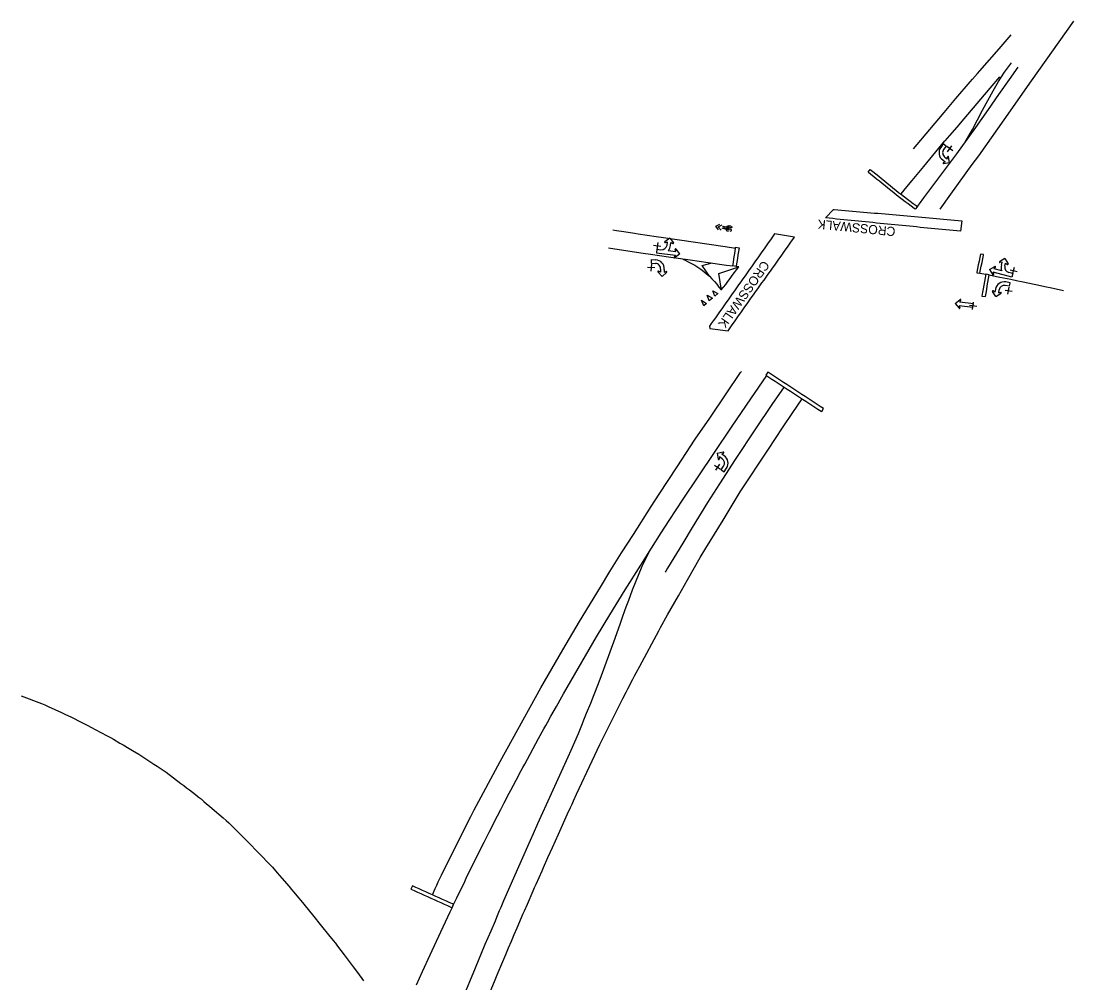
# Model space of a CAD drawing. Extents: x 1723992 to 1732080, y 650782 to 665122.
# Drawn here: x 1730247 to 1730822, y 652932 to 653458 of the extents above; entities that cross this region are included whole.
import ezdxf

# ---------------------------------------------------------------- set-up
doc = ezdxf.new("R2010")
doc.units = 0
doc.layers.add('SURVEY - TRAFFIC CONTROL - Pavement Marking - Points - Locators', color=7, linetype='Continuous')
doc.layers.add('SURVEY - TRAFFIC CONTROL - Pavement Marking with Text', color=7, linetype='Continuous')

msp = doc.modelspace()

# ---------------------------------------------------------------- linework, layer by layer
at = {"layer": 'SURVEY - TRAFFIC CONTROL - Pavement Marking - Points - Locators'}
for p, q in [((1730755.42, 653386.72), (1730752.19, 653389.08)), ((1730752.63, 653386.28), (1730754.98, 653389.52)), ((1730595.99, 653334.51), (1730592.02, 653335.01)), ((1730594.26, 653336.74), (1730593.75, 653332.77)), ((1730592.68, 653322.84), (1730588.68, 653323.09)), ((1730590.8, 653324.96), (1730590.56, 653320.97)), ((1730788.16, 653319.4), (1730789.16, 653323.27)), ((1730786.73, 653321.83), (1730790.6, 653320.83)), ((1730785.6, 653308.42), (1730786.31, 653312.36)), ((1730783.99, 653310.74), (1730787.92, 653310.04)), ((1730764.59, 653302.42), (1730768.56, 653301.89)), ((1730766.31, 653300.17), (1730766.84, 653304.14)), ((1730625.24, 653215.15), (1730628.55, 653212.89)), ((1730628.03, 653215.67), (1730625.76, 653212.37))]:
    msp.add_line(p, q, dxfattribs=at)
at = {"layer": 'SURVEY - TRAFFIC CONTROL - Pavement Marking with Text'}
for p, q in [((1730750.22, 653390.5), (1730748.87, 653388.65)), ((1730751.81, 653389.35), (1730750.22, 653390.5)), ((1730751.81, 653389.35), (1730750.46, 653387.49)), ((1730749.96, 653381.77), (1730751.27, 653380.82)), ((1730751.27, 653380.82), (1730750.22, 653380.18)), ((1730753.72, 653380.26), (1730750.38, 653379.73)), ((1730751.12, 653383.37), (1730752.42, 653382.42)), ((1730752.42, 653382.42), (1730752.71, 653383.61)), ((1730753.72, 653380.26), (1730753.19, 653383.59)), ((1730600.84, 653339.1), (1730598.17, 653337.03)), ((1730599.57, 653336.92), (1730598.38, 653336.6)), ((1730599.36, 653335.32), (1730599.57, 653336.92)), ((1730600.84, 653339.1), (1730602.91, 653336.43)), ((1730601.32, 653335.07), (1730601.52, 653336.68)), ((1730601.52, 653336.68), (1730602.59, 653336.07)), ((1730593.79, 653333.05), (1730593.54, 653331.1)), ((1730593.54, 653331.1), (1730603.97, 653329.77)), ((1730593.79, 653333.05), (1730596.06, 653332.76)), ((1730599.97, 653332.27), (1730604.22, 653331.73)), ((1730603.97, 653329.77), (1730603.36, 653328.71)), ((1730606.39, 653330.46), (1730603.72, 653328.39)), ((1730604.22, 653331.73), (1730603.9, 653332.91)), ((1730606.39, 653330.46), (1730604.33, 653333.13)), ((1730590.83, 653325.42), (1730590.95, 653327.38)), ((1730590.83, 653325.42), (1730593.12, 653325.28)), ((1730590.95, 653327.38), (1730593.24, 653327.24)), ((1730638.59, 653323.42), (1730637.1, 653323.63)), ((1730775.56, 653321.95), (1730778.47, 653323.66)), ((1730778.06, 653322.32), (1730778.8, 653323.3)), ((1730783.93, 653327.91), (1730781.02, 653326.2)), ((1730782.4, 653325.92), (1730781.18, 653325.75)), ((1730781.99, 653324.35), (1730782.4, 653325.92)), ((1730783.9, 653323.86), (1730784.3, 653325.42)), ((1730783.93, 653327.91), (1730785.64, 653325)), ((1730784.3, 653325.42), (1730785.28, 653324.68)), ((1730596.63, 653318.16), (1730594.39, 653320.69)), ((1730595.79, 653320.54), (1730594.68, 653321.08)), ((1730595.89, 653322.15), (1730595.79, 653320.54)), ((1730596.63, 653318.16), (1730599.16, 653320.4)), ((1730597.85, 653322.03), (1730597.75, 653320.42)), ((1730597.75, 653320.42), (1730598.92, 653320.82)), ((1730770.28, 653319.9), (1730773.54, 653319.32)), ((1730775.56, 653321.95), (1730777.28, 653319.04)), ((1730787.74, 653317.78), (1730777.56, 653320.42)), ((1730777.56, 653320.42), (1730777.73, 653319.2)), ((1730782.2, 653321.25), (1730778.06, 653322.32)), ((1730788.24, 653319.68), (1730786.01, 653320.26)), ((1730788.24, 653319.68), (1730787.74, 653317.78)), ((1730778.77, 653311.18), (1730778.48, 653309.58)), ((1730786.39, 653312.81), (1730784.13, 653313.22)), ((1730786.73, 653314.75), (1730784.47, 653315.15)), ((1730786.39, 653312.81), (1730786.73, 653314.75)), ((1730624.25, 653306.31), (1730622.47, 653304.75)), ((1730627.21, 653308.93), (1730625.49, 653307.41)), ((1730756.82, 653303.47), (1730759.51, 653305.52)), ((1730779.04, 653307.13), (1730777.11, 653309.9)), ((1730778.48, 653309.58), (1730777.45, 653310.25)), ((1730779.04, 653307.13), (1730781.81, 653309.06)), ((1730780.7, 653310.83), (1730780.42, 653309.24)), ((1730780.42, 653309.24), (1730781.62, 653309.5)), ((1730620.9, 653303.36), (1730619.51, 653302.13)), ((1730756.82, 653303.47), (1730758.87, 653300.79)), ((1730766.44, 653301.18), (1730758.99, 653302.19)), ((1730758.99, 653302.19), (1730759.3, 653301)), ((1730759.25, 653304.14), (1730759.87, 653305.2)), ((1730766.71, 653303.13), (1730759.25, 653304.14)), ((1730766.44, 653301.18), (1730766.71, 653303.13)), ((1730626.76, 653221.67), (1730630.08, 653222.29)), ((1730626.76, 653221.67), (1730627.38, 653218.35)), ((1730628.12, 653219.55), (1730627.87, 653218.34)), ((1730629.45, 653218.63), (1730628.12, 653219.55)), ((1730629.23, 653221.17), (1730630.26, 653221.84)), ((1730630.57, 653220.26), (1730629.23, 653221.17)), ((1730628.92, 653212.63), (1730630.22, 653214.53)), ((1730630.55, 653211.52), (1730631.85, 653213.42)), ((1730628.92, 653212.63), (1730630.55, 653211.52))]:
    msp.add_line(p, q, dxfattribs=at)
for points in [[(1730748.51, 653354.94), (1730754.39, 653363.03), (1730766.12, 653379.23), (1730769.64, 653384.09), (1730776.66, 653393.82), (1730783.54, 653403.64), (1730798.47, 653424.93), (1730821.64, 653457.63)], [(1730733.93, 653387.8), (1730742.97, 653398.49), (1730750.73, 653407.64), (1730757.2, 653415.26), (1730764.98, 653424.4), (1730766.29, 653425.91), (1730768.92, 653428.92), (1730770.23, 653430.43), (1730780.73, 653442.5), (1730787.33, 653450.08)], [(1730736.12, 653356.29), (1730737.3, 653357.9), (1730739.68, 653361.12), (1730757.62, 653385.16), (1730767.98, 653399.58), (1730774.93, 653409.36), (1730780.7, 653417.53), (1730786.45, 653425.72), (1730791.2, 653432.48)], [(1730762.17, 653391.45), (1730766.15, 653398.39), (1730771.64, 653409.05), (1730777.53, 653419.51), (1730780.52, 653424.71), (1730783.79, 653429.74), (1730787.59, 653434.9)], [(1730780.95, 653427.12), (1730775.76, 653421.02), (1730770.58, 653414.93), (1730761.52, 653404.26), (1730757.61, 653399.71), (1730753.71, 653395.15), (1730751.16, 653392.18)], [(1730727.08, 653363.14), (1730728.14, 653364.42), (1730729.41, 653365.96), (1730733.24, 653370.58), (1730739.62, 653378.28), (1730751.16, 653392.18)], [(1730736.12, 653356.29), (1730734.97, 653354.82), (1730734.29, 653355.33), (1730732.69, 653356.54), (1730731.09, 653357.74), (1730729.5, 653358.94), (1730727.9, 653360.15), (1730726.3, 653361.35), (1730724.73, 653362.59), (1730723.18, 653363.84), (1730721.62, 653365.09), (1730720.06, 653366.35), (1730718.5, 653367.6), (1730716.95, 653368.85), (1730715.39, 653370.1), (1730713.83, 653371.36), (1730712.27, 653372.61), (1730710.71, 653373.86), (1730709.16, 653375.11), (1730710.32, 653376.64)], [(1730710.32, 653376.64), (1730711.88, 653375.39), (1730713.44, 653374.13), (1730714.99, 653372.88), (1730716.55, 653371.62), (1730718.1, 653370.37), (1730719.66, 653369.11), (1730721.22, 653367.86), (1730722.77, 653366.6), (1730724.33, 653365.35), (1730725.88, 653364.09), (1730727.45, 653362.85), (1730729.04, 653361.64), (1730730.64, 653360.44), (1730732.23, 653359.23), (1730733.83, 653358.02), (1730735.42, 653356.82), (1730736.12, 653356.29)], [(1730760.42, 653348.53), (1730759.6, 653342.8), (1730757.61, 653343), (1730755.62, 653343.19), (1730753.63, 653343.39), (1730751.64, 653343.59), (1730749.65, 653343.79), (1730747.66, 653343.98), (1730745.67, 653344.18), (1730743.68, 653344.38), (1730741.69, 653344.58), (1730739.7, 653344.77), (1730737.71, 653344.97), (1730735.72, 653345.17), (1730733.73, 653345.37), (1730731.74, 653345.57), (1730729.75, 653345.76), (1730727.76, 653345.96), (1730725.77, 653346.16), (1730723.78, 653346.35), (1730721.79, 653346.55), (1730719.8, 653346.75), (1730717.81, 653346.95), (1730715.82, 653347.15), (1730713.83, 653347.34), (1730711.83, 653347.54), (1730709.84, 653347.74), (1730707.85, 653347.94), (1730705.86, 653348.13), (1730703.87, 653348.33), (1730701.88, 653348.53), (1730699.89, 653348.73), (1730697.9, 653348.92), (1730695.91, 653349.12), (1730693.92, 653349.32), (1730691.93, 653349.52), (1730689.94, 653349.71), (1730687.95, 653349.91), (1730685.96, 653350.11), (1730690.35, 653354.79)], [(1730690.35, 653354.79), (1730690.69, 653354.76), (1730692.69, 653354.58), (1730694.68, 653354.41), (1730696.67, 653354.23), (1730698.66, 653354.05), (1730700.66, 653353.87), (1730702.65, 653353.69), (1730704.64, 653353.52), (1730706.63, 653353.34), (1730708.62, 653353.16), (1730710.62, 653352.98), (1730712.61, 653352.8), (1730714.6, 653352.63), (1730716.59, 653352.45), (1730718.58, 653352.27), (1730720.58, 653352.09), (1730722.57, 653351.91), (1730724.56, 653351.74), (1730726.55, 653351.56), (1730728.54, 653351.38), (1730730.54, 653351.2), (1730732.53, 653351.02), (1730734.52, 653350.84), (1730736.51, 653350.67), (1730738.51, 653350.49), (1730740.5, 653350.31), (1730742.49, 653350.13), (1730744.48, 653349.95), (1730746.48, 653349.78), (1730748.47, 653349.6), (1730750.46, 653349.42), (1730752.45, 653349.24), (1730754.44, 653349.07), (1730756.44, 653348.89), (1730758.43, 653348.71), (1730760.42, 653348.53)], [(1730627.48, 653343.58), (1730625.94, 653345.53), (1730628.15, 653346.68)], [(1730628.95, 653343.36), (1730627.3, 653345.22), (1730629.51, 653346.37)], [(1730632.66, 653344.95), (1730632.28, 653345.14), (1730632.28, 653345.14), (1730632.25, 653345.65), (1730632.71, 653345.84), (1730633.34, 653345.89), (1730633.99, 653345.77), (1730634.49, 653345.5), (1730634.79, 653345.19), (1730634.79, 653345.19), (1730634.77, 653344.96), (1730634.52, 653344.73), (1730634.04, 653344.73), (1730633.51, 653344.78)], [(1730569.82, 653343.56), (1730571.79, 653343.26), (1730575.75, 653342.66), (1730581.68, 653341.76), (1730583.65, 653341.46), (1730593.53, 653339.96), (1730597.49, 653339.36), (1730631.11, 653334.46), (1730636.79, 653333.62)], [(1730668.98, 653339.56), (1730658.13, 653341.36), (1730656.98, 653339.73), (1730655.82, 653338.09), (1730654.67, 653336.46), (1730653.52, 653334.83), (1730652.36, 653333.2), (1730651.21, 653331.56), (1730650.05, 653329.93), (1730648.9, 653328.3), (1730647.74, 653326.66), (1730646.59, 653325.03), (1730645.43, 653323.4), (1730644.28, 653321.76), (1730643.12, 653320.13), (1730641.97, 653318.5), (1730640.81, 653316.87), (1730639.66, 653315.23), (1730638.5, 653313.6), (1730637.35, 653311.97), (1730636.19, 653310.33), (1730635.04, 653308.7), (1730633.89, 653307.07), (1730632.73, 653305.43), (1730631.58, 653303.8), (1730630.42, 653302.17), (1730629.27, 653300.54), (1730628.11, 653298.9), (1730626.96, 653297.27), (1730625.8, 653295.64), (1730624.65, 653294), (1730623.49, 653292.37), (1730622.5, 653290.96)], [(1730633.24, 653343.38), (1730630.37, 653344.2), (1730629.7, 653344.39), (1730629.76, 653344.55)], [(1730629.93, 653345.15), (1730630.01, 653345.36), (1730630.08, 653345.53)], [(1730633.12, 653344.49), (1730630.81, 653345.19), (1730630.01, 653345.36)], [(1730633.12, 653344.49), (1730630.37, 653344.2), (1730630.81, 653345.19), (1730633.43, 653345.26)], [(1730633.84, 653342.83), (1730634.4, 653343.02), (1730634.54, 653343.16), (1730634.66, 653343.38), (1730634.54, 653343.58), (1730634.3, 653343.79), (1730633.53, 653343.94), (1730632.88, 653343.98), (1730632.21, 653343.94), (1730631.79, 653343.74), (1730631.72, 653343.43), (1730632.25, 653343.05), (1730632.93, 653342.9)], [(1730622.5, 653290.96), (1730622.83, 653289.65), (1730632.68, 653288.51), (1730633.83, 653290.14), (1730634.99, 653291.77), (1730636.15, 653293.4), (1730637.31, 653295.03), (1730638.47, 653296.66), (1730639.63, 653298.29), (1730640.79, 653299.92), (1730641.95, 653301.55), (1730643.11, 653303.18), (1730644.27, 653304.81), (1730645.42, 653306.44), (1730646.58, 653308.07), (1730647.74, 653309.7), (1730648.9, 653311.33), (1730650.06, 653312.95), (1730651.22, 653314.58), (1730652.38, 653316.21), (1730653.54, 653317.84), (1730654.7, 653319.47), (1730655.85, 653321.1), (1730657.01, 653322.73), (1730658.17, 653324.36), (1730659.33, 653325.99), (1730660.49, 653327.62), (1730661.65, 653329.25), (1730662.81, 653330.88), (1730663.97, 653332.51), (1730665.13, 653334.14), (1730666.29, 653335.77), (1730667.45, 653337.4), (1730668.6, 653339.03), (1730668.98, 653339.56)], [(1730637.1, 653323.63), (1730635.31, 653323.87), (1730635.61, 653325.84), (1730635.91, 653327.82), (1730636.21, 653329.8), (1730636.51, 653331.78), (1730636.81, 653333.75), (1730636.86, 653334.12), (1730638.77, 653333.81)], [(1730567.37, 653333.73), (1730580.39, 653331.8), (1730586.32, 653330.93), (1730590.27, 653330.32), (1730600.15, 653328.82), (1730612.02, 653327.15), (1730621.92, 653325.79), (1730631.81, 653324.37), (1730635.31, 653323.87)], [(1730638.77, 653333.81), (1730638.45, 653331.84), (1730638.12, 653329.87), (1730637.8, 653327.9), (1730637.48, 653325.92), (1730637.15, 653323.95), (1730637.1, 653323.63)], [(1730772.29, 653330.13), (1730770.58, 653330.38), (1730770.19, 653328.42), (1730769.79, 653326.46), (1730769.4, 653324.5), (1730769.01, 653322.54), (1730768.62, 653320.58), (1730768.53, 653320.16), (1730770.28, 653319.9)], [(1730770.28, 653319.9), (1730770.67, 653321.87), (1730771.05, 653323.83), (1730771.44, 653325.79), (1730771.82, 653327.75), (1730772.2, 653329.71), (1730772.29, 653330.13)], [(1730608.06, 653327.67), (1730609.21, 653327.08), (1730610.99, 653326.18), (1730612.77, 653325.27), (1730614.5, 653324.26), (1730616.17, 653323.17), (1730617.84, 653322.07), (1730619.43, 653320.87), (1730621, 653319.63), (1730622.51, 653318.33), (1730623.87, 653316.87), (1730625.23, 653315.41), (1730626.5, 653313.87), (1730627.76, 653312.32), (1730629.02, 653310.77), (1730630.22, 653312.21), (1730631.42, 653313.81), (1730632.61, 653315.41), (1730633.81, 653317.01), (1730635.01, 653318.62), (1730636.2, 653320.22), (1730637.4, 653321.82), (1730638.59, 653323.42)], [(1730622.51, 653318.33), (1730618.56, 653324.2), (1730623.94, 653325.5)], [(1730629.08, 653310.69), (1730627.69, 653319.77), (1730638.59, 653323.42)], [(1730773.54, 653319.32), (1730773.16, 653317.36), (1730772.78, 653315.39), (1730772.4, 653313.43), (1730772.02, 653311.47), (1730771.65, 653309.51), (1730771.24, 653307.42), (1730773.29, 653307.13)], [(1730773.29, 653307.13), (1730773.63, 653309.1), (1730773.98, 653311.07), (1730774.33, 653313.04), (1730774.67, 653315.01), (1730775.02, 653316.98), (1730775.37, 653318.99), (1730773.54, 653319.32)], [(1730775.37, 653318.99), (1730779.28, 653318.2), (1730781.24, 653317.8), (1730787.1, 653316.62), (1730791.01, 653315.83), (1730792.96, 653315.43), (1730800.77, 653313.79), (1730806.62, 653312.54), (1730808.57, 653312.12), (1730816.02, 653310.52)], [(1730622.47, 653304.75), (1730621.3, 653307.88), (1730624.25, 653306.31)], [(1730625.49, 653307.41), (1730624.44, 653310.38), (1730627.21, 653308.93)], [(1730619.51, 653302.13), (1730618.17, 653305.21), (1730620.9, 653303.36)], [(1730471.25, 652980.39), (1730472.79, 652983.87), (1730473.6, 652985.7), (1730474.44, 652987.51), (1730476.13, 652991.13), (1730481.48, 653001.85), (1730492.24, 653023.27), (1730494.09, 653026.81), (1730508.17, 653053.26), (1730514.89, 653065.53), (1730530.41, 653093.47), (1730534.41, 653100.39), (1730542.44, 653114.2), (1730551.48, 653129.75), (1730562.97, 653148.49), (1730568.18, 653157.02), (1730574.53, 653167.19), (1730580.98, 653177.31), (1730590.64, 653192.49), (1730595.02, 653199.18), (1730604.89, 653214.23), (1730614.81, 653229.24), (1730622.67, 653240.83), (1730631.66, 653254.07), (1730639.53, 653265.65), (1730639.99, 653266.33)], [(1730683.88, 653244.39), (1730684.78, 653245.95), (1730683.11, 653247.05), (1730681.44, 653248.15), (1730679.77, 653249.25), (1730678.1, 653250.35), (1730676.43, 653251.45), (1730674.76, 653252.55), (1730673.09, 653253.65), (1730671.42, 653254.75), (1730669.75, 653255.85), (1730668.08, 653256.95), (1730666.41, 653258.05), (1730664.74, 653259.15), (1730663.07, 653260.25), (1730661.4, 653261.35), (1730659.73, 653262.45), (1730658.06, 653263.55), (1730656.4, 653264.65), (1730654.73, 653265.75), (1730654.48, 653265.91), (1730653.34, 653264.28)], [(1730482.8, 652975.18), (1730484.53, 652978.79), (1730488.86, 652987.79), (1730489.73, 652989.58), (1730497.65, 653005.72), (1730499.45, 653009.29), (1730502.14, 653014.64), (1730506.71, 653023.52), (1730508.54, 653027.07), (1730510.38, 653030.62), (1730513.18, 653035.92), (1730514.11, 653037.68), (1730516.91, 653042.98), (1730519.72, 653048.27), (1730520.67, 653050.03), (1730521.62, 653051.79), (1730529.21, 653065.85), (1730532.12, 653071.09), (1730533.09, 653072.84), (1730534.05, 653074.58), (1730535.99, 653078.08), (1730538.91, 653083.31), (1730541.86, 653088.53), (1730542.85, 653090.26), (1730544.81, 653093.74), (1730552.78, 653107.59), (1730560.88, 653121.37), (1730568.13, 653133.33), (1730576.5, 653146.95), (1730584.99, 653160.5), (1730590.91, 653169.69), (1730596.23, 653178.15), (1730600.57, 653184.86), (1730608.22, 653196.58), (1730624.94, 653221.49), (1730635, 653236.41), (1730645.2, 653251.25), (1730653.82, 653263.99)], [(1730653.34, 653264.28), (1730655.02, 653263.18), (1730656.7, 653262.09), (1730658.37, 653261), (1730660.05, 653259.91), (1730661.72, 653258.82), (1730663.4, 653257.73), (1730665.08, 653256.64), (1730666.75, 653255.55), (1730668.43, 653254.46), (1730670.1, 653253.36), (1730671.78, 653252.27), (1730673.45, 653251.18), (1730675.13, 653250.09), (1730676.81, 653249), (1730678.48, 653247.91), (1730680.16, 653246.82), (1730681.83, 653245.73), (1730683.51, 653244.64), (1730683.88, 653244.39)], [(1730663.28, 653257.8), (1730656.61, 653248.2), (1730647.61, 653234.97), (1730636.6, 653218.27), (1730627.95, 653204.81), (1730621.54, 653194.67), (1730613.08, 653181.1), (1730607.92, 653172.54), (1730599.69, 653158.83), (1730598.66, 653157.12), (1730598.35, 653156.61)], [(1730502.79, 652927.5), (1730505.1, 652933.03), (1730506.63, 652936.72), (1730509.7, 652944.09), (1730511.24, 652947.78), (1730512, 652949.62), (1730512.77, 652951.47), (1730514.34, 652955.14), (1730515.93, 652958.8), (1730517.52, 652962.47), (1730519.9, 652967.97), (1730520.69, 652969.8), (1730521.49, 652971.63), (1730523.07, 652975.3), (1730526.25, 652982.63), (1730527.04, 652984.46), (1730527.83, 652986.29), (1730529.45, 652989.95), (1730531.08, 652993.59), (1730531.9, 652995.42), (1730534.34, 653000.89), (1730536.79, 653006.36), (1730540.05, 653013.65), (1730544.94, 653024.59), (1730546.63, 653028.21), (1730547.47, 653030.02), (1730548.32, 653031.83), (1730550, 653035.45), (1730558.43, 653053.55), (1730562.7, 653062.58), (1730563.59, 653064.36), (1730564.49, 653066.15), (1730575.23, 653087.57), (1730577.02, 653091.14), (1730577.91, 653092.92), (1730580.66, 653098.25), (1730581.6, 653100.01), (1730582.55, 653101.76), (1730584.45, 653105.28), (1730594.88, 653124.62), (1730595.82, 653126.38), (1730596.77, 653128.13), (1730598.68, 653131.64), (1730599.67, 653133.38), (1730605.59, 653143.81), (1730610.52, 653152.49), (1730617.43, 653164.66), (1730620.54, 653169.79), (1730629.95, 653185.12), (1730639.37, 653200.46), (1730654.8, 653223.82), (1730662.51, 653235.5), (1730668.07, 653243.81), (1730673.15, 653251.38)], [(1730487.06, 652922.11), (1730491.64, 652933.19), (1730494.71, 652940.56), (1730500.09, 652953.46), (1730503.24, 652960.81), (1730505.59, 652966.32), (1730506.38, 652968.16), (1730507.95, 652971.83), (1730508.73, 652973.66), (1730510.3, 652977.33), (1730519.11, 652997.46), (1730524.76, 653010.25), (1730526.4, 653013.89), (1730528.84, 653019.36), (1730536.23, 653035.75), (1730545.32, 653055.74), (1730546.98, 653059.37), (1730550.95, 653068.53), (1730553.22, 653074.08), (1730553.96, 653075.93), (1730555.45, 653079.64), (1730557.67, 653085.2), (1730559.13, 653088.92), (1730559.86, 653090.78), (1730562.79, 653098.21), (1730565.62, 653105.68), (1730571.07, 653120.7), (1730573.07, 653126.34), (1730573.74, 653128.22), (1730575.07, 653131.99), (1730576.41, 653135.76), (1730577.08, 653137.64), (1730578.42, 653141.4), (1730580.47, 653147.03), (1730585.81, 653159.96), (1730589.86, 653167.99)], [(1730246.52, 653089.18), (1730257.72, 653084.91), (1730259.59, 653084.19), (1730261.4, 653083.36), (1730268.66, 653080.01), (1730270.47, 653079.18), (1730274.09, 653077.48), (1730279.4, 653074.71), (1730282.94, 653072.87), (1730284.72, 653071.94), (1730290.03, 653069.17), (1730293.57, 653067.32), (1730295.34, 653066.4), (1730297.06, 653065.38), (1730300.5, 653063.35), (1730302.22, 653062.33), (1730305.66, 653060.3), (1730307.38, 653059.28), (1730310.78, 653057.19), (1730312.45, 653056.09), (1730315.8, 653053.91), (1730319.14, 653051.72), (1730320.81, 653050.63), (1730322.49, 653049.54), (1730325.83, 653047.35), (1730333.79, 653041.33), (1730335.38, 653040.11), (1730336.96, 653038.9), (1730338.55, 653037.69), (1730341.72, 653035.26), (1730343.31, 653034.04), (1730344.85, 653032.78), (1730346.37, 653031.49), (1730347.89, 653030.19), (1730349.41, 653028.89), (1730350.93, 653027.6), (1730357.01, 653022.41), (1730358.53, 653021.12), (1730360, 653019.76), (1730361.42, 653018.36), (1730371.34, 653008.5), (1730375.5, 653004.18), (1730383.79, 652995.52), (1730386.4, 652992.49), (1730387.7, 652990.98), (1730389.01, 652989.46), (1730392.93, 652984.92), (1730394.23, 652983.41), (1730395.54, 652981.89), (1730398.09, 652978.82), (1730399.35, 652977.27), (1730405.66, 652969.52), (1730410.71, 652963.31), (1730414.49, 652958.66), (1730417, 652955.55), (1730418.22, 652953.97), (1730419.44, 652952.38), (1730423.1, 652947.63), (1730427.87, 652941.2), (1730430.21, 652937.96), (1730433.49, 652933.44)], [(1730460.34, 652985.3), (1730459.48, 652983.59), (1730461.3, 652982.76), (1730463.13, 652981.94), (1730464.95, 652981.12), (1730466.77, 652980.3), (1730468.59, 652979.47), (1730470.42, 652978.65), (1730472.24, 652977.83), (1730474.06, 652977.01), (1730475.88, 652976.18), (1730477.7, 652975.36), (1730479.53, 652974.54), (1730481.35, 652973.72), (1730482.06, 652973.4), (1730482.8, 652975.18)], [(1730482.8, 652975.18), (1730482.21, 652975.45), (1730480.39, 652976.27), (1730478.57, 652977.09), (1730476.75, 652977.91), (1730474.92, 652978.73), (1730473.1, 652979.55), (1730471.28, 652980.38), (1730469.45, 652981.2), (1730467.63, 652982.02), (1730465.81, 652982.84), (1730463.99, 652983.66), (1730462.16, 652984.48), (1730460.34, 652985.3)], [(1730462.6, 652931.2), (1730464.23, 652934.85), (1730465.86, 652938.5), (1730469.98, 652947.59), (1730475.83, 652960.29), (1730480.97, 652971.11), (1730481.83, 652972.91), (1730482.06, 652973.4)]]:
    msp.add_lwpolyline(points, dxfattribs=at)
for centre, radius, start, end in [((1730752.85, 653385.75), 4.92, 143.97128, 233.97128), ((1730752.85, 653385.75), 2.95, 143.97128, 233.97128), ((1730750.35, 653379.97), 0.246, 121.52301, 278.97128), ((1730752.95, 653383.55), 0.246, 8.97128, 166.46444), ((1730596.44, 653335.69), 2.95, 262.74242, 352.74242), ((1730598.32, 653336.84), 0.246, 127.74242, 285.23558), ((1730596.44, 653335.69), 4.92, 315.87252, 352.74242), ((1730602.71, 653336.28), 0.246, 240.29416, 37.74242), ((1730603.57, 653328.58), 0.246, 150.29416, 307.74242), ((1730604.13, 653332.98), 0.246, 37.74242, 195.23558), ((1730592.94, 653322.33), 2.95, 356.49532, 86.49532), ((1730592.94, 653322.33), 4.92, 356.49532, 86.49532), ((1730778.6, 653323.45), 0.246, 322.98548, 120.47865), ((1730781.14, 653325.99), 0.246, 120.47865, 277.92691), ((1730786.75, 653323.12), 4.92, 165.47865, 202.34854), ((1730786.75, 653323.12), 2.95, 165.47865, 255.47865), ((1730785.43, 653324.88), 0.246, 232.98548, 30.47865), ((1730594.58, 653320.86), 0.246, 64.00216, 221.49532), ((1730599, 653320.59), 0.246, 311.49532, 108.94358), ((1730777.49, 653319.16), 0.246, 210.47865, 7.92691), ((1730783.61, 653310.31), 4.92, 79.87444, 169.87444), ((1730783.61, 653310.31), 2.95, 79.87444, 169.87444), ((1730759.66, 653305.32), 0.246, 329.86687, 127.31514), ((1730777.31, 653310.04), 0.246, 57.42618, 214.87444), ((1730781.67, 653309.26), 0.246, 304.87444, 102.3676), ((1730759.07, 653300.94), 0.246, 217.31514, 14.8083), ((1730630.13, 653222.05), 0.246, 303.14633, 100.5946), ((1730627.79, 653216.2), 4.92, 325.5946, 55.5946), ((1730627.63, 653218.39), 0.246, 190.5946, 348.08776), ((1730627.79, 653216.2), 2.95, 325.5946, 55.5946)]:
    msp.add_arc(centre, radius, start, end, dxfattribs=at)

# ---------------------------------------------------------------- texts
for rotation, p in [(174.31792, (1730724.34, 653345.03)), (234.74525, (1730651.69, 653327.22))]:
    msp.add_text('CROSSWALK', height=5, rotation=rotation, dxfattribs=at).set_placement(p)

doc.saveas('drawing.dxf')
